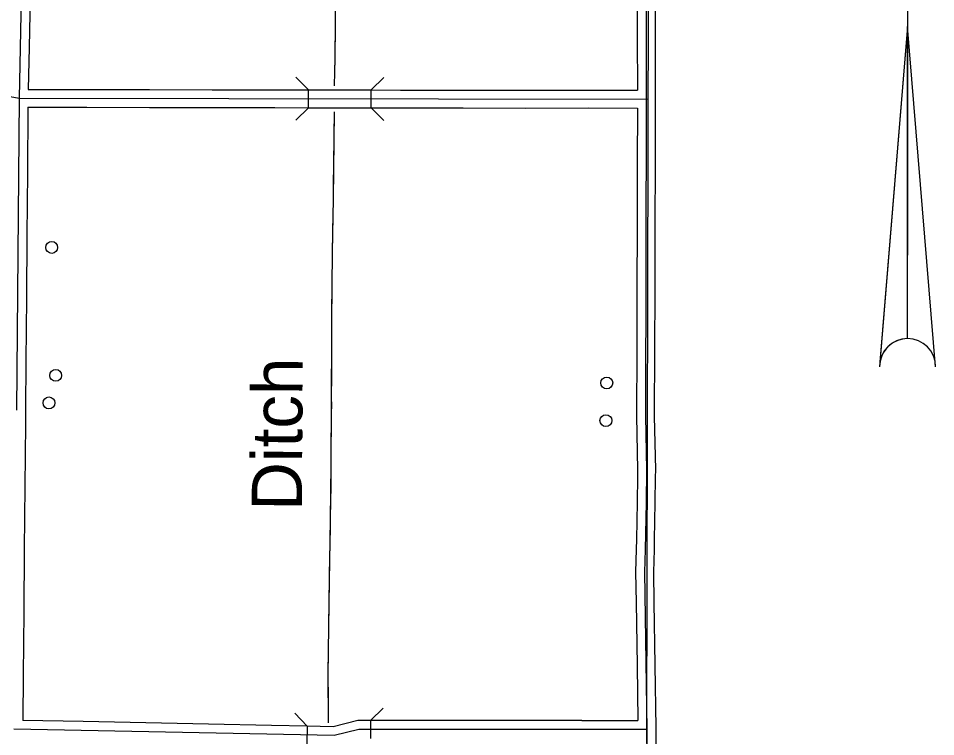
# Model space of a CAD drawing. Extents: x -4306 to 3843, y 131 to 8341.
# Drawn here: x 1424 to 2659, y 1864 to 2831 of the extents above; entities that cross this region are included whole.
import ezdxf

# ---------------------------------------------------------------- set-up
doc = ezdxf.new("R2010")
doc.units = 0
for name, color, linetype in [('32', 7, 'Continuous'), ('38', 7, 'Continuous'), ('50', 7, 'Continuous'), ('56', 7, 'Continuous'), ('57', 7, 'Continuous')]:
    doc.layers.add(name, color=color, linetype=linetype)

msp = doc.modelspace()

# ---------------------------------------------------------------- linework, layer by layer
at = {"layer": '32'}
for p, q in [((1433.9, 3130), (1424.9, 2723.1)), ((2270.3, 1873.5), (2273, 3127.4)), ((2270.3, 1873.5), (2273, 3127.4)), ((1440.3, 2876.3), (1438.4, 2791.8)), ((2257.3, 2874.9), (2257.4, 2804.7)), ((2269.3, 2874.9), (2269.5, 2717.3)), ((2269.3, 2874.9), (2269.5, 2717.3)), ((2281.3, 2874.9), (2281.4, 2804.7)), ((2257.4, 2804.7), (2257.5, 2733.9)), ((2281.4, 2804.7), (2281.5, 2720.3)), ((1005.6, 2802.5), (1424.9, 2723.1)), ((1438.4, 2791.8), (1437.2, 2735.1)), ((1437.2, 2735.1), (1516, 2734.9)), ((1516, 2734.9), (1600.5, 2734.8)), ((1600.5, 2734.8), (1685, 2734.6)), ((1685, 2734.6), (1769.5, 2734.5)), ((1769.5, 2734.5), (1814.8, 2734.4)), ((1814.6, 2710.4), (1814.6, 2734.4)), ((1814.6, 2734.4), (1854, 2734.4)), ((1854, 2734.4), (1899.1, 2734.3)), ((1899.1, 2710.3), (1899.1, 2734.3)), ((1899.1, 2734.3), (1938.5, 2734.2)), ((1938.5, 2734.2), (2023, 2734.1)), ((2023, 2734.1), (2107.5, 2733.9)), ((2107.5, 2733.9), (2191.9, 2734)), ((2191.9, 2734), (2257.5, 2733.9)), ((1424.9, 2723.1), (1421.6, 2303.3)), ((1424.9, 2723.1), (2272.1, 2721.7)), ((2281.5, 2720.3), (2281.5, 2717.2)), ((1436.8, 2711), (1436.1, 2623.1)), ((1436.8, 2711), (1516, 2710.9)), ((1516, 2710.9), (1600.5, 2710.8)), ((1600.5, 2710.8), (1685, 2710.6)), ((1685, 2710.6), (1769.5, 2710.5)), ((1769.5, 2710.5), (1814.6, 2710.4)), ((1814.6, 2710.4), (1853.9, 2710.4)), ((1853.9, 2710.4), (1899.1, 2710.3)), ((1899.1, 2710.3), (1938.4, 2710.2)), ((1938.4, 2710.2), (2022.9, 2710.1)), ((2022.9, 2710.1), (2107.4, 2709.9)), ((2107.4, 2709.9), (2191.9, 2710)), ((2191.9, 2710), (2257.5, 2709.9)), ((2257.5, 2709.9), (2257.3, 2635.8)), ((2269.5, 2717.3), (2268.3, 2295.1)), ((2269.5, 2717.3), (2268.3, 2295.1)), ((2281.5, 2717.2), (2281.3, 2635.7)), ((2257.3, 2635.8), (2257, 2551.3)), ((2281.3, 2635.7), (2281, 2551.2)), ((1436.1, 2623.1), (1435.4, 2538.6)), ((2257, 2551.3), (2256.8, 2466.8)), ((2281, 2551.2), (2280.8, 2466.7)), ((1435.4, 2538.6), (1434.8, 2454.1)), ((2256.8, 2466.8), (2256.6, 2382.3)), ((2280.8, 2466.7), (2280.6, 2382.2)), ((1434.8, 2454.1), (1434.1, 2369.6)), ((2256.6, 2382.3), (2256.3, 2297.8)), ((2280.6, 2382.2), (2280.3, 2297.8)), ((1434.1, 2369.6), (1433.6, 2303.2)), ((1433.6, 2303.2), (1433.4, 2285.1)), ((2256.3, 2297.8), (2256.3, 2295)), ((2280.3, 2297.8), (2280.3, 2295.2)), ((2256.3, 2295), (2257.7, 2222.8)), ((2268.3, 2295.1), (2269.7, 2222.9)), ((2268.3, 2295.1), (2269.7, 2222.9)), ((2280.3, 2295.2), (2281.7, 2222.9)), ((1433.4, 2285.1), (1432.7, 2200.6)), ((2257.6, 2213.5), (2257.1, 2179.4)), ((2257.7, 2222.8), (2257.6, 2213.5)), ((2269.7, 2222.9), (2269.1, 2179.2)), ((2269.7, 2222.9), (2269.1, 2179.2)), ((2281.6, 2213.1), (2281.1, 2179)), ((2281.7, 2222.9), (2281.6, 2213.1)), ((1432.7, 2200.6), (1431.9, 2116.1)), ((2257.1, 2179.4), (2256.2, 2129)), ((2269.1, 2179.2), (2268, 2115.9)), ((2269.1, 2179.2), (2268, 2115.9)), ((2281.1, 2179), (2280.2, 2128.6)), ((2256.2, 2129), (2256, 2116.2)), ((2280.2, 2128.6), (2280, 2115.7)), ((1431.9, 2116.1), (1431.1, 2031.6)), ((2256, 2116.2), (2255.1, 2085.3)), ((2268, 2115.9), (2267.1, 2085.2)), ((2268, 2115.9), (2267.1, 2085.2)), ((2280, 2115.7), (2279.1, 2085.1)), ((2255.1, 2085.3), (2255.7, 2044.2)), ((2267.1, 2085.2), (2270.3, 1873.5)), ((2267.1, 2085.2), (2270.3, 1873.5)), ((2279.1, 2085.1), (2279.7, 2044.5)), ((2255.7, 2044.2), (2257, 1959.7)), ((2279.7, 2044.5), (2281, 1960.1)), ((1431.1, 2031.6), (1430.3, 1947.2)), ((2257, 1959.7), (2258.1, 1885.7)), ((2281, 1960.1), (2282.3, 1875.6)), ((1430.3, 1947.2), (1429.8, 1885.7)), ((1511.2, 1884), (1429.8, 1885.7)), ((1595.6, 1882.3), (1511.2, 1884)), ((1680.1, 1880.6), (1595.6, 1882.3)), ((1764.6, 1878.9), (1680.1, 1880.6)), ((1812.7, 1878), (1764.6, 1878.9)), ((1812.7, 1878), (1812.2, 1854)), ((1847.8, 1877.2), (1812.7, 1878)), ((1880.9, 1885.4), (1847.8, 1877.2)), ((1898.3, 1885.4), (1880.9, 1885.4)), ((1898.3, 1885.4), (1898.3, 1861.4)), ((1932.3, 1885.4), (1898.3, 1885.4)), ((2016.8, 1885.4), (1932.3, 1885.4)), ((2101.3, 1885.4), (2016.8, 1885.4)), ((2182.8, 1885.7), (2101.3, 1885.4)), ((2182.8, 1885.7), (2258.1, 1885.7)), ((1849.1, 1865.2), (1417.7, 1873.9)), ((1882.4, 1873.4), (1849.1, 1865.2)), ((2270.3, 1873.5), (1882.4, 1873.4)), ((2270.3, 1873.5), (2270.1, 1664.6)), ((2270.3, 1873.5), (2270.1, 1664.6)), ((2275.6, 1463.4), (2270.3, 1873.5)), ((2275.6, 1463.4), (2270.3, 1873.5)), ((2282.3, 1873.6), (2282.2, 1790.9)), ((2282.3, 1875.6), (2282.3, 1873.6))]:
    msp.add_line(p, q, dxfattribs=at)
at = {"layer": '38'}
for p, q in [((1814.6, 2722.4), (1814.6, 2722.4)), ((1899.1, 2722.3), (1899.1, 2722.3))]:
    msp.add_line(p, q, dxfattribs=at)
for points in [[(1814.6, 2734.4), (1797.7, 2751.4)], [(1916.1, 2751.2), (1899.1, 2734.3)], [(1797.6, 2693.5), (1814.6, 2710.4)], [(1899.1, 2710.3), (1916, 2693.3)], [(1898.3, 1885.4), (1915.3, 1902.3)], [(1796, 1895.3), (1812.7, 1878)]]:
    msp.add_lwpolyline(points, dxfattribs=at)
at = {"layer": '50'}
for p, q in [((2621.3, 2996.4), (2621.3, 2511.9)), ((2621.3, 2819.6), (2584, 2368.1)), ((2621.3, 2399.7), (2621.3, 2819.6))]:
    msp.add_line(p, q, dxfattribs=at)
msp.add_lwpolyline([(2659.1, 2361.8), (2621.3, 2819.6), (2583.5, 2361.8)], dxfattribs=at)
for start, end in [(0, 180), (90, 170.5511)]:
    msp.add_arc((2621.3, 2361.8), 37.8, start, end, dxfattribs=at)
at = {"layer": '56'}
for points in [[(1853.1, 3126.3), (1852.8, 3049.4), (1851.2, 2917), (1849.9, 2777.6), (1849.4, 2740)], [(1850.3, 2820.1), (1849.9, 2777.6), (1849.6, 2756.7)], [(1849, 2705), (1847.9, 2587.8), (1846.4, 2515.9), (1845.7, 2422.9), (1845.3, 2295.3), (1844.3, 2183.2), (1842.4, 2073), (1840.8, 1948.9), (1841.2, 1882.6)], [(1849, 2705), (1848.7, 2673.3)], [(1848.5, 2652.2), (1847.9, 2588.8)], [(1847.5, 2567.7), (1846.4, 2515.9), (1846.3, 2504.4)], [(1846.2, 2483.3), (1845.7, 2422.9), (1845.7, 2419.9)], [(1845.6, 2398.8), (1845.4, 2335.4)], [(1845.4, 2314.3), (1845.3, 2295.3), (1844.9, 2250.9)], [(1844.7, 2229.8), (1844.5, 2198.1)], [(1844.5, 2198.1), (1844.3, 2183.2), (1844, 2166.4)], [(1843.7, 2145.3), (1842.6, 2082)], [(1842.2, 2060.8), (1841.4, 1997.5)], [(1841.2, 1976.3), (1840.8, 1948.9), (1841, 1913)]]:
    msp.add_lwpolyline(points, dxfattribs=at)
at = {"layer": '57'}
for centre in [(1468.8, 2522.3), (1474.2, 2350.1), (2216.2, 2339.9), (1465.1, 2313), (2215.1, 2289.2)]:
    msp.add_circle(centre, 8, dxfattribs=at)

# ---------------------------------------------------------------- texts
at = {"layer": '56'}
msp.add_text('Ditch', height=67.59, rotation=89.7133, dxfattribs=at).set_placement((1805.7, 2167.8))

doc.saveas('drawing.dxf')
